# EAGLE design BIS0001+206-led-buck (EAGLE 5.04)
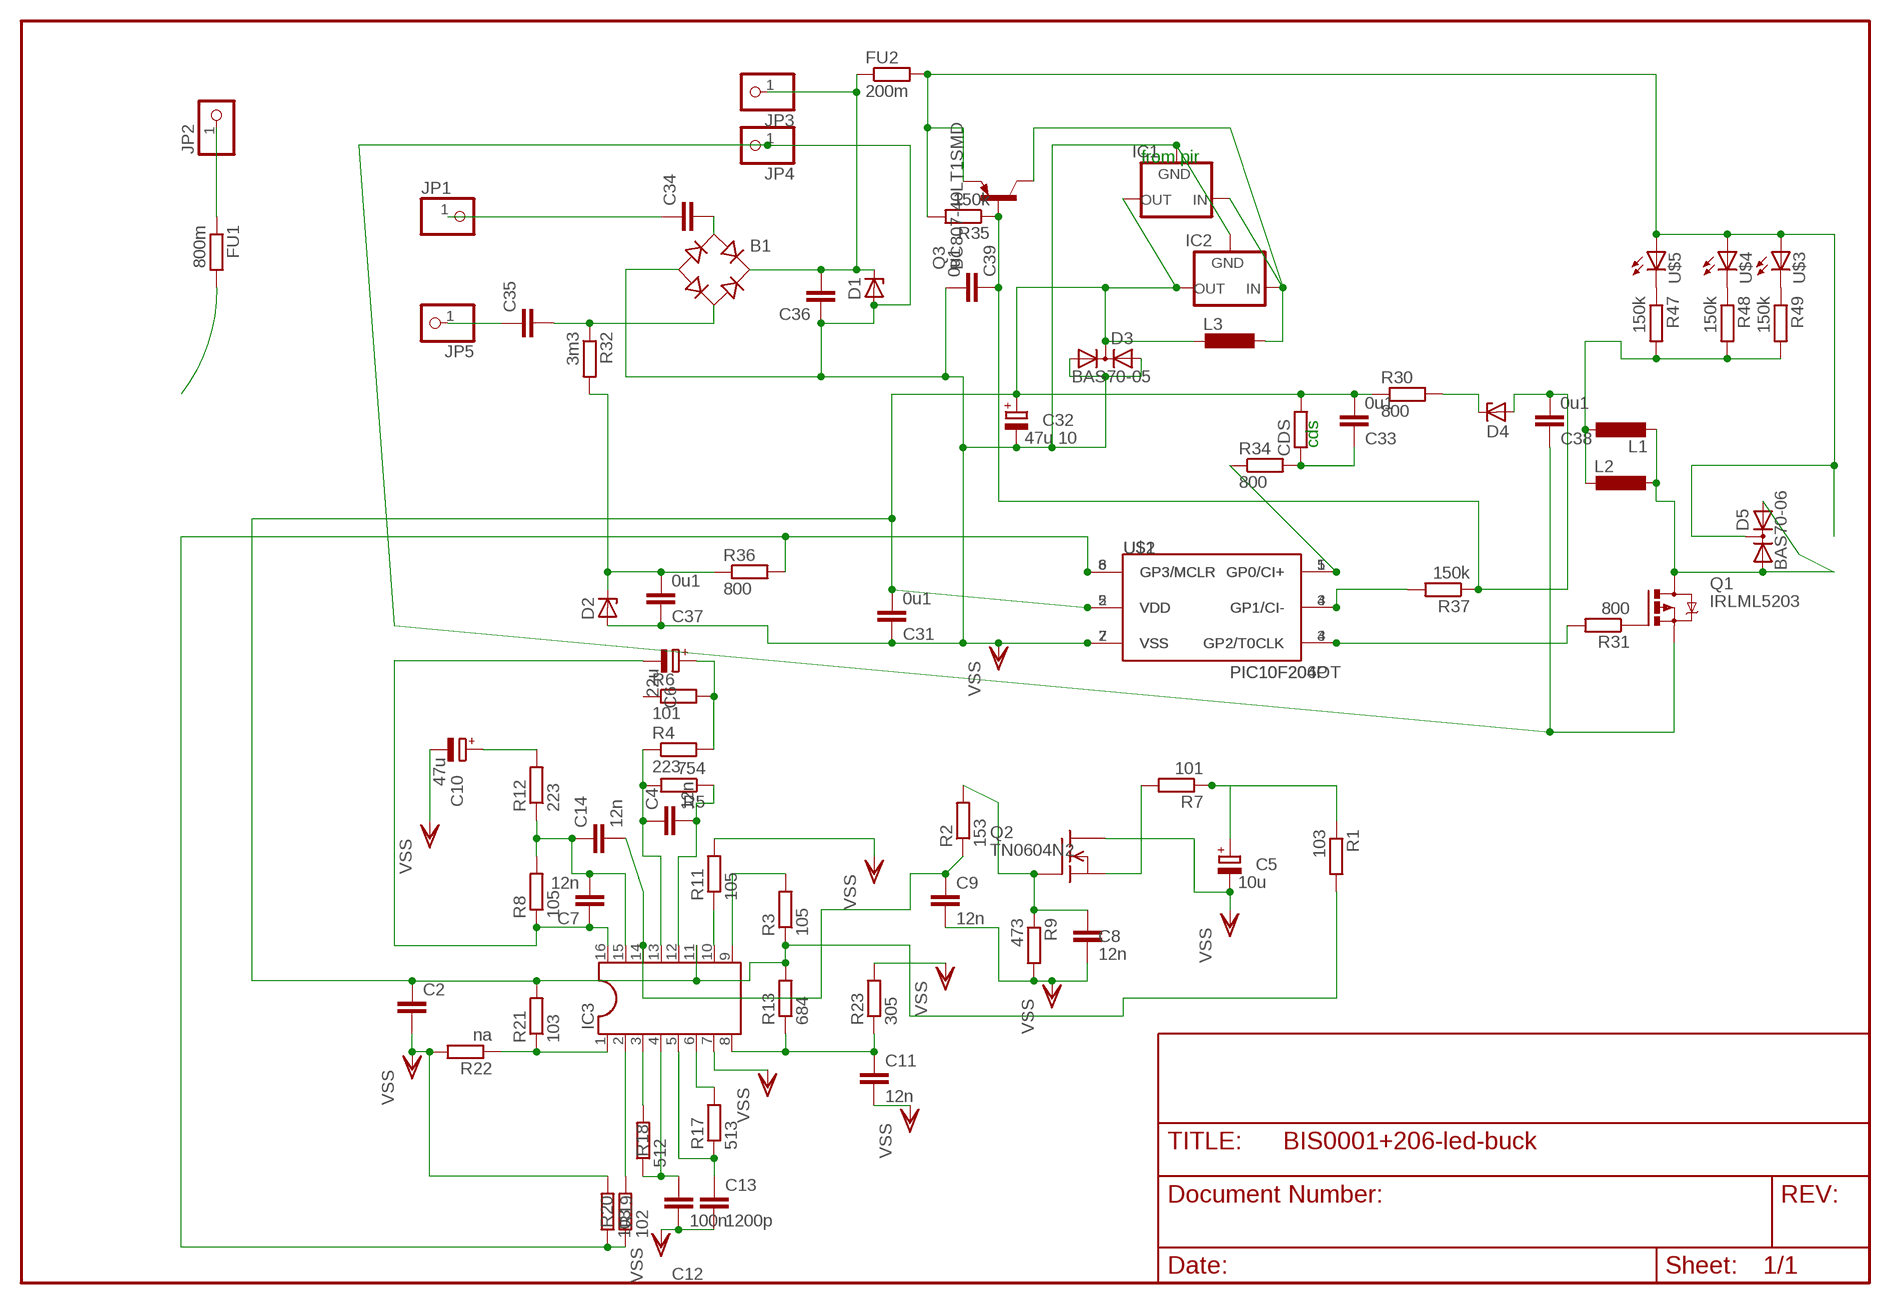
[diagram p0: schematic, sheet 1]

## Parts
B1  RB1A  [RB1A]
C2  C-EUC0805  [C0805]
C4  12n  C-EUC0805  [C0805]
C5  10u  CPOL-EUE2.5-5  [E2,5-5]
C6  22u  CPOL-EUE2.5-5  [E2,5-5]
C7  12n  C-EUC0805  [C0805]
C8  12n  C-EUC0805  [C0805]
C9  12n  C-EUC0805  [C0805]
C10  47u  CPOL-EUE2.5-5  [E2,5-5]
C11  12n  C-EUC0805  [C0805]
C12  100n  C-EUC0805  [C0805]
C13  1200p  C-EUC0805  [C0805]
C14  12n  C-EUC0805  [C0805]
C31  0u1  C-EUC1206  [C1206]
C32  47u 10  CPOL-EUE2.5-5  [E2,5-5]
C33  0u1  C-EUC1206  [C1206]
C34  C-EU050-025X075  [C050-025X075]
C35  C-EU050-025X075  [C050-025X075]
C36  C-EU050-025X075  [C050-025X075]
C37  0u1  C-EUC1206  [C1206]
C38  0u1  C-EUC1206  [C1206]
C39  0u1  C-EUC1206  [C1206]
CDS  R-EU_0207/5V  [0207/5V]
D1  ZENER-DIODEZD-7.5  [ZDIO-7.5]
D2  ZENER-DIODESOT23  [SOT23]
D3  BAS70-05  [SOT23]
D4  ZENER-DIODESOT23  [SOT23]
D5  BAS70-06  [SOT23]
FU1  800m  R-EU_0204/5  [0204/5]
FU2  200m  R-EU_0204/5  [0204/5]
IC1  XC63FPT  [TO92]
IC2  XC63FPP  [SOT89R]
IC3  DIL16SO16  [SO16]
JP1  PINHD-1X1  [1X01]
JP2  PINHD-1X1  [1X01]
JP3  PINHD-1X1  [1X01]
JP4  PINHD-1X1  [1X01]
JP5  PINHD-1X1  [1X01]
L1  L-EUL5650M  [L5650M]
L2  L-EU0207/7  [0207/7]
L3  L-EU0204V  [0204V]
Q1  IRLML5203  [MICRO3]
Q2  TN0604N2  [TO-39]
Q3  BC807-40LT1SMD  [SOT23-BEC]
R1  103  R-EU_R0805  [R0805]
R2  153  R-EU_R0805  [R0805]
R3  105  R-EU_R0805  [R0805]
R4  223  R-EU_R0805  [R0805]
R5  754  R-EU_R0805  [R0805]
R6  101  R-EU_R0805  [R0805]
R7  101  R-EU_R0805  [R0805]
R8  105  R-EU_R0805  [R0805]
R9  473  R-EU_R0805  [R0805]
R11  105  R-EU_R0805  [R0805]
R12  223  R-EU_R0805  [R0805]
R13  684  R-EU_R0805  [R0805]
R17  513  R-EU_R0805  [R0805]
R18  512  R-EU_R0805  [R0805]
R19  102  R-EU_R0805  [R0805]
R20  103  R-EU_R0805  [R0805]
R21  103  R-EU_R0805  [R0805]
R22  na  R-EU_R0805  [R0805]
R23  305  R-EU_R0805  [R0805]
R30  800  R-EU_R1206  [R1206]
R31  800  R-EU_R1206  [R1206]
R32  3m3  R-EU_R1206  [R1206]
R34  800  R-EU_R1206  [R1206]
R35  150k  R-EU_R0805  [R0805]
R36  800  R-EU_R1206  [R1206]
R37  150k  R-EU_R1206  [R1206]
R47  150k  R-EU_R1206  [R1206]
R48  150k  R-EU_R1206  [R1206]
R49  150k  R-EU_R1206  [R1206]
U$1  PIC10F206P  [DIL8]
U$2  PIC10F204OT  [SOT23-6]
U$3  LED5MM  [LED5MM]
U$4  LED5MM  [LED5MM]
U$5  LED5MM  [LED5MM]

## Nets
N$1: B1.+ C36.2 D1.C FU2.1 JP3.1
N$4: FU1.1 JP2.1
N$6: D4.3(C) R30.2
N$7: D5.3(C) FU2.2 Q3.E R35.2 U$3.A U$4.A U$5.A
N$8: C38.2 C39.1 D4.1(A) Q3.B R35.1 R37.1
N$9: FU1.2
N$10: Q1.1(G) R31.1
N$11: IC3.1 R21.1 R22.1
N$12: R19.1 R20.1 R36.2 U$1.8(GP3/MCLR) U$2.6(GP3/MCLR)
N$13: R37.2 U$1.4(GP1/CI-) U$2.3(GP1/CI-)
N$14: R31.2 U$1.3(GP2/T0CLK) U$2.4(GP2/T0CLK)
N$15: IC1.2(IN) IC2.2(IN) L3.1 Q3.C
N$16: C37.2 D2.3(C) R32.2 R36.1
N$17: C35.1 JP5.1
N$18: B1.AC2 C35.2 R32.1
N$20: C34.1 JP1.1
N$22: L1.1 L2.2 R47.2 R48.2 R49.2
N$23: C33.1 CDS.1 R34.2
N$24: IC3.2 R19.2
N$25: C12.1 IC3.4 R18.1
N$26: D5.1(A1) D5.2(A2) L1.2 L2.1 Q1.3(D)
N$27: IC3.3 R18.2
N$28: C11.1 IC3.8 R13.1 R23.1
N$29: R34.1 U$1.5(GP0/CI+) U$2.1(GP0/CI+)
N$30: C13.1 IC3.5 R17.1
N$31: IC3.6 R17.2
N$32: IC3.10 R11.1
N$33: B1.AC1 C34.2
N$34: C4.2 IC3.12 R5.1
N$35: C4.1 IC3.13 R4.1 R5.2
N$36: IC3.9 R3.2
N$37: C6.+ R4.2 R6.2
N$38: R47.1 U$5.K(C)
N$39: C9.1 C14.2 IC3.14 R2.1
N$40: C7.2 C14.1 IC3.15 R8.2 R12.1
N$41: C6.- C7.1 IC3.16 R8.1
N$42: Q2.1(S) R7.2
N$43: C5.+ R1.1 R7.1
N$44: C10.+ R12.2
N$46: C8.1 Q2.2(G) R2.2 R9.1
N$54: R48.1 U$4.K(C)
N$55: R49.1 U$3.K(C)
V2CC: C2.1 C31.2 C32.+ C33.2 CDS.2 D3.3(C) IC1.3(OUT) IC2.3(OUT) IC3.11 L3.2 R1.2 R3.1 R13.2 R21.2 R30.1 U$1.2(VDD) U$2.5(VDD)
VSS: B1.- C2.2 C5.- C8.2 C9.2 C10.- C11.2 C12.2 C13.2 C31.1 C32.- C36.1 C37.1 C38.1 C39.2 D1.A D2.1(A) D3.1(A1) D3.2(A2) IC1.1(GND) IC2.1(GND) IC3.7 JP4.1 Q1.2(S) Q2.3(D) R9.2 R11.2 R20.2 R22.2 R23.2 U$1.7(VSS) U$2.2(VSS)
Unconnected: R6.1

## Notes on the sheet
- from pir
- cds

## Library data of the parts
B1 = rectifier:RB1A: RECTIFIER 1 A
C2 C4 C7-C9 C11-C14 = rcl-2:C-EU: CAPACITOR, European symbol
C5 C6 C10 C32 = rcl:CPOL-EU: POLARIZED CAPACITOR, European symbol
C31 C33-C39 = rcl:C-EU: CAPACITOR, European symbol
CDS = rcl(2):R-EU_: RESISTOR, European symbol
D1 D2 D4 = diode-1:ZENER-DIODE: Z-Diode
D3 = diode-1:BAS70-05: Silicon Schottky Diodes General-purpose diode for high-speed switching
D5 = diode-1:BAS70-06: Silicon Schottky Diodes General-purpose diode for high-speed switching
FU1 FU2 R30-R32 R34-R37 R47-R49 = rcl:R-EU_: RESISTOR, European symbol
IC1 IC2 = v-reg:XC63FP: Positiv Voltage Regulators www.torex.co.jp/english/product/pro02/pdf/0201_xc62fp.pdf
IC3 = ic-package:DIL16: Dual In Line / Socket
JP1-JP5 = pinhead:PINHD-1X1: PIN HEADER
L1 = rcl-2:L-EU: INDUCTOR, European symbol
L2 L3 = rcl:L-EU: INDUCTOR, European symbol
Q1 = transistor-power:IRLML5203: HEXFET P-Channel Power MOSFET
Q2 = transistor-fet:TN0604N2: N-Channel Enhancement MOSFET 40V; 4A; 0,85Ohm
Q3 = transistor-pnp:BC807*: PNP Transistror
R1-R9 R11-R13 R17-R23 = rcl-2:R-EU_: RESISTOR, European symbol
U$1 U$2 = microchip-3:PIC10F2*: uPC nW 0,25/0,5k Program Flash memory Comparator
U$3-U$5 = led(3):LED: LED

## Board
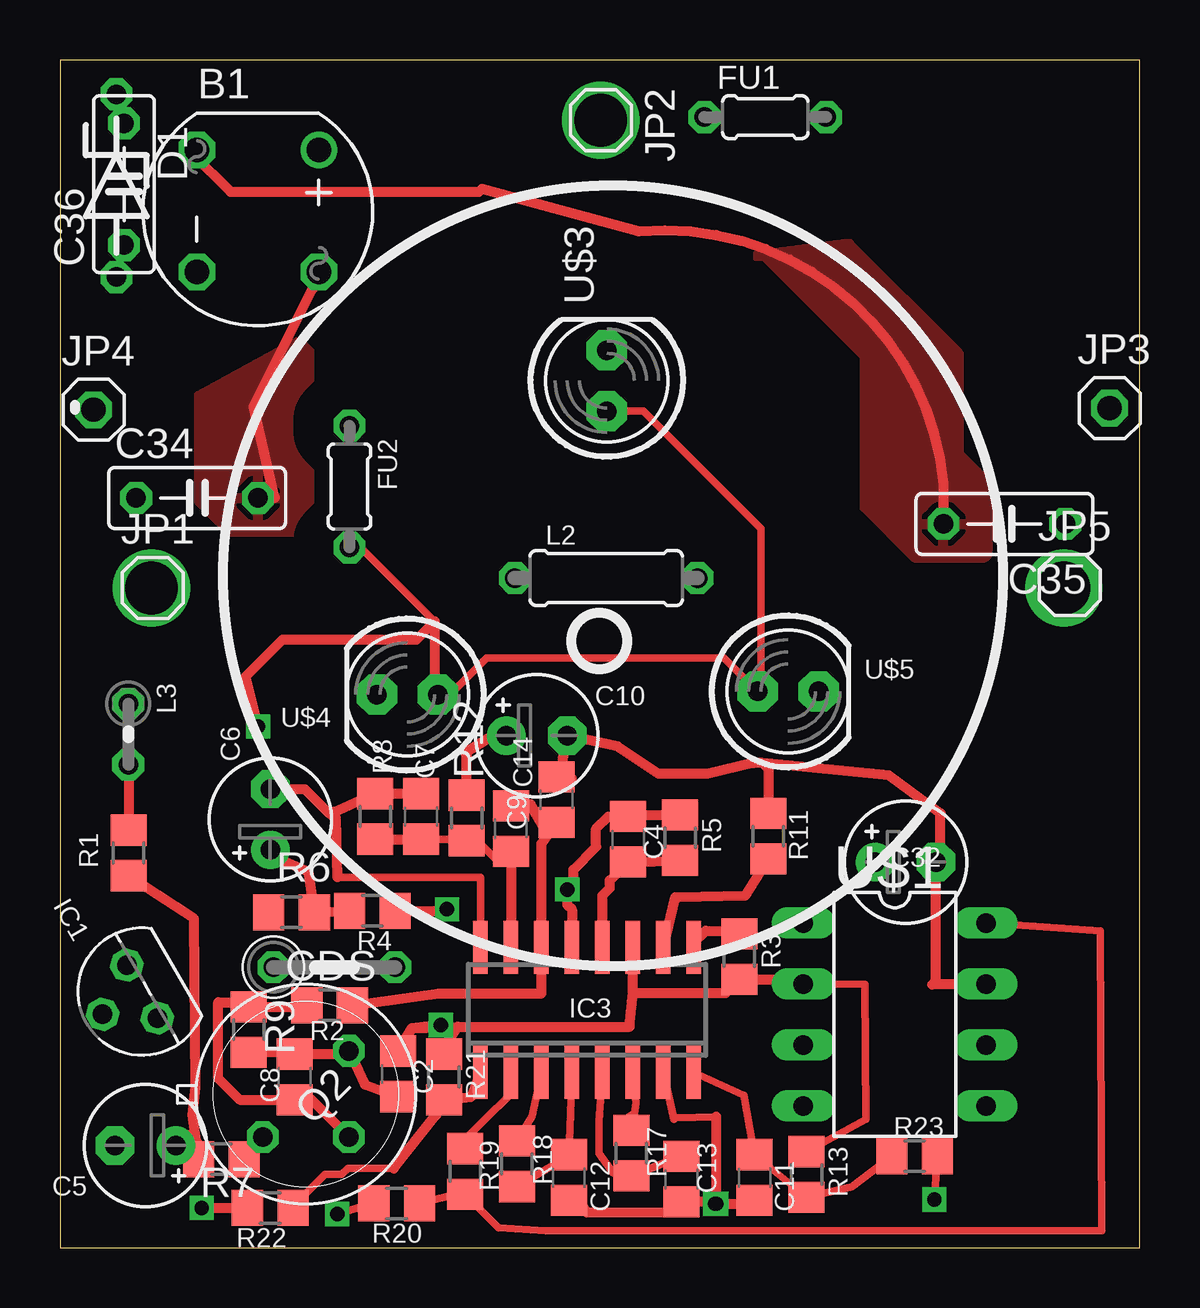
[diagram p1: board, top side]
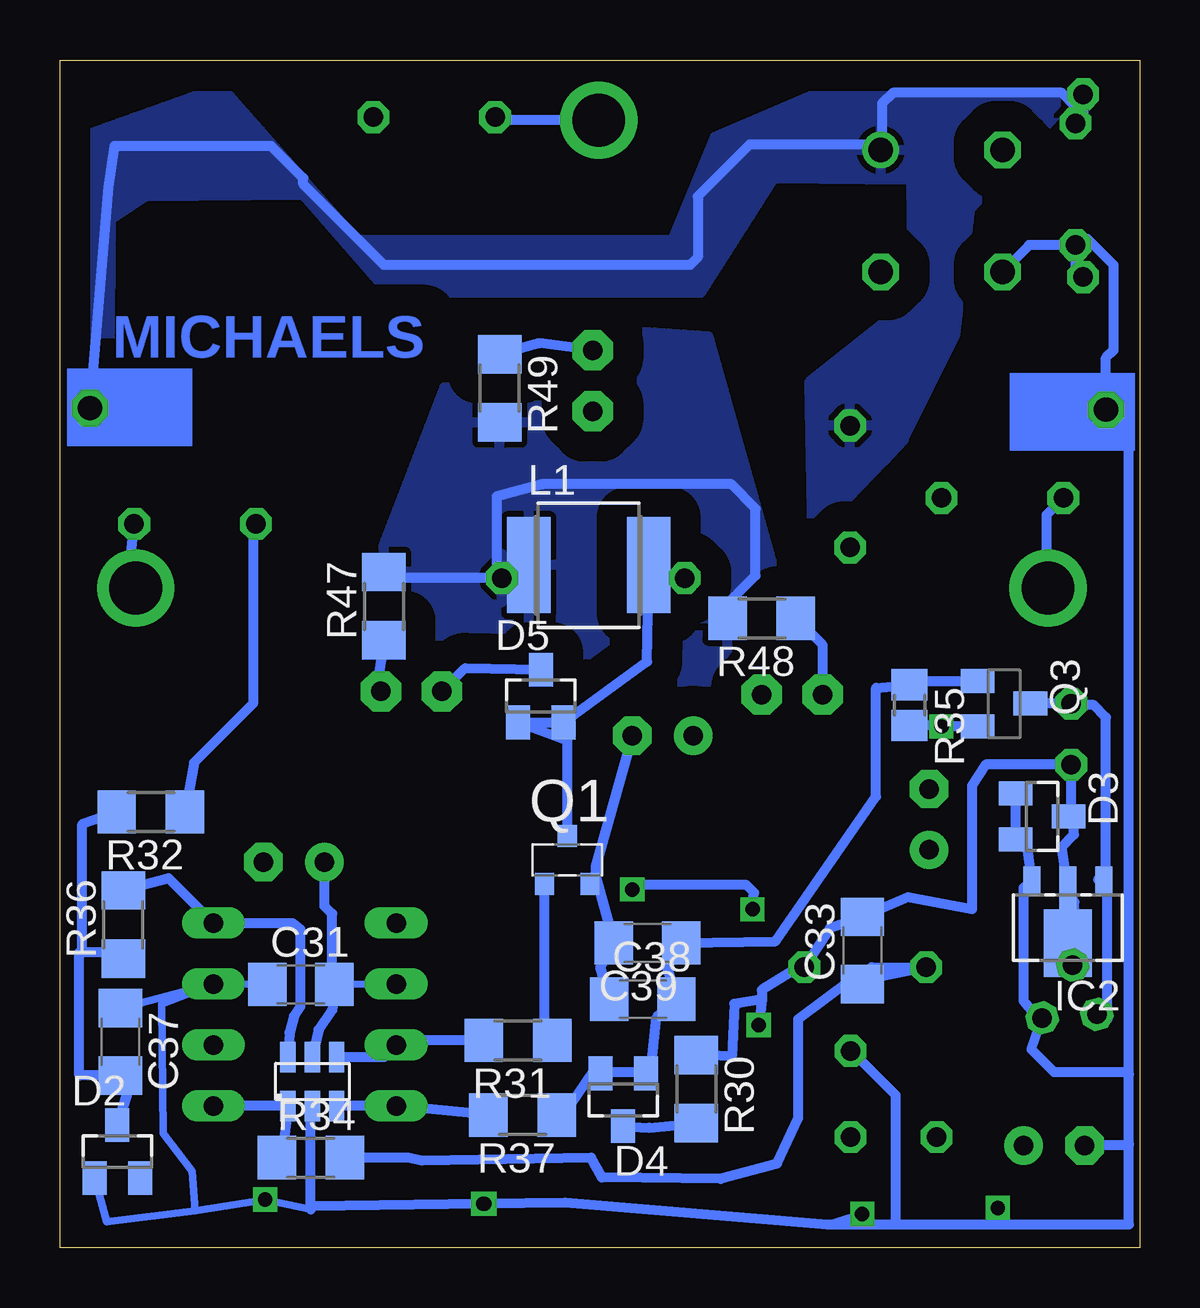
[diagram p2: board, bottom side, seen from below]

Size 45 x 49.5 mm. Coordinates in mm from the lower left corner, seen from the top.
Outline: 0,0 45,0 45,49.5 0,49.5 0,0
Copper layers (1*16): Top 0.035mm / dielectric 1.5mm / Bottom 0.035mm
Design rules "default": minimum track width 10mil, minimum drill 24mil, track to track 8mil, track to pad 8mil, pad to pad 8mil, via to via 8mil, smd to smd 8mil, copper to edge 40mil, drill to drill 8mil, minimum pad ring 10mil, minimum via ring 8mil, stop-mask expansion 4mil, vias tented up to drill 0mil, thermal gap 10mil

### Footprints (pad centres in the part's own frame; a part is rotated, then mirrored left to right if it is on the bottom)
RB1A = drill 1.016 round: + -2.54,2.54 | drill 1.016 octagon: - 2.54,-2.54; AC1 2.54,2.54; AC2 -2.54,-2.54
C0805 = smd 1.3 x 1.5: 1 -0.95,0; 2 0.95,0
E2,5-5 = drill 0.813 pad 1.6 round: + -1.27,0 | drill 0.813 pad 1.6 octagon: - 1.27,0
C1206 = smd 1.6 x 1.8: 1 -1.4,0; 2 1.4,0
C050-025X075 = drill 0.813 octagon: 1 -2.54,0; 2 2.54,0
0207/5V = drill 0.813 octagon: 1 -2.54,0; 2 2.54,0
ZDIO-7.5 = drill 0.813 octagon: A 3.81,0; C -3.81,0
SOT23 = smd 1 x 1.4: 1 -0.95,-1.1; 2 0.95,-1.1; 3 0,1.1
0204/5 = drill 0.813 octagon: 1 -2.54,0; 2 2.54,0
TO92 = drill 0.813 octagon: 1 -1.27,0; 2 0,1.905; 3 1.27,0
SOT89R = smd 0.7 x 1.1: 1 1.5,-1.75; 2 -1.5,-1.75 | smd 0.7 x 1.8: 3 0,-1.4 | smd 2 x 2.8: 4 0,0.9
SO16 = smd 0.6 x 2.2: 1 -4.445,-2.6; 2 -3.175,-2.6; 3 -1.905,-2.6; 4 -0.635,-2.6; 5 0.635,-2.6; 6 1.905,-2.6; 7 3.175,-2.6; 8 4.445,-2.6; 9 4.445,2.6; 10 3.175,2.6; 11 1.905,2.6; 12 0.635,2.6; 13 -0.635,2.6; 14 -1.905,2.6; 15 -3.175,2.6; 16 -4.445,2.6
1X01 = drill 1.016 octagon: 1 0,0
L5650M = smd 1.8 x 4: 1 -2.5,0; 2 2.5,0
0207/7 = drill 0.813 octagon: 1 -3.81,0; 2 3.81,0
0204V = drill 0.813 octagon: 1 -1.27,0; 2 1.27,0
MICRO3 = smd 0.8 x 0.9: 1 -0.95,-1; 2 0.95,-1; 3 0,1
TO-39 = drill 0.813 octagon: 1 0,-2.54; 2 2.54,0; 3 0,2.54
SOT23-BEC = smd 1 x 1.4: B -0.95,-1.1; C 0,1.1; E 0.95,-1.1
R0805 = smd 1.3 x 1.5: 1 -0.95,0; 2 0.95,0
R1206 = smd 1.6 x 1.803: 1 -1.422,0; 2 1.422,0
R0805' = smd 1.3 x 1.5: 1 -0.85,0; 2 0.85,0
DIL8 = drill 0.813 long: 1 -3.81,-3.81; 2 -1.27,-3.81; 3 1.27,-3.81; 4 3.81,-3.81; 5 3.81,3.81; 6 1.27,3.81; 7 -1.27,3.81; 8 -3.81,3.81
SOT23-6 = smd 0.635 x 1.27: 1 -1.016,-1.016; 2 0,-1.016; 3 1.016,-1.016; 4 1.016,1.016; 5 0,1.016; 6 -1.016,1.016
LED5MM = drill 0.813 pad 1.676 octagon: A -1.27,0; K 1.27,0

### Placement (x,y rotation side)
B1  8.25,43.21 270 top
C2  14.1,7.24 270 top
C4  23.69,17.02 270 top
C5  3.56,4.25 180 top
C6  8.76,17.84 90 top
C7  15.05,17.97 270 top
C8  9.78,7.11 90 top
C9  20.7,18.67 90 top
C10  19.88,21.34 0 top
C11  28.96,2.92 270 top
C12  21.21,2.92 270 top
C13  25.91,2.86 270 top
C14  18.8,17.46 90 top
C31  34.96,10.96 0 bottom
C32  35.24,16.07 0 top
C33  11.56,12.38 90 bottom
C34  5.71,31.24 0 top
C35  39.37,30.16 180 top
C36  2.67,44.32 90 top
C37  42.48,8.57 270 bottom
C38  20.7,10.35 0 bottom
C39  20.51,12.7 180 bottom
CDS  11.43,11.68 0 top
D1  2.35,44.26 270 top
D2  42.61,4 0 bottom
D3  4.06,17.97 270 bottom
D4  21.53,6.16 180 bottom
D5  24.96,22.99 0 bottom
FU1  29.4,47.12 0 top
FU2  12.07,31.72 270 top
IC1  3.42,10.67 120 top
IC2  2.98,13.59 180 bottom
IC3  21.97,9.91 0 top
JP1  3.87,27.5 0 top
JP2  22.54,46.99 270 top
JP3  43.75,34.99 0 top
JP4  1.4,34.92 0 top
JP5  42.1,27.62 0 top
L1  22.96,28.44 0 bottom
L2  22.77,27.91 0 top
L3  2.85,21.4 270 top
Q1  23.85,16.16 0 bottom
Q2  10.25,6.4 315 top
Q3  5.65,22.67 270 bottom
R1  2.86,16.45 90 top
R2  11.24,10.1 180 top
R3  28.32,12.13 90 top
R4  13.02,14.03 180 top
R5  25.84,17.08 90 top
R6  9.65,13.97 0 top
R7  6.73,3.68 0 top
R8  13.14,17.97 270 top
R9  7.87,9.08 270 top
R11  29.53,17.14 90 top
R12  16.95,17.91 90 top
R13  31.11,3.05 90 top
R17  23.81,3.94 90 top
R18  19.05,3.49 90 top
R19  16.89,3.17 90 top
R20  14.03,1.84 180 top
R21  16,7.11 90 top
R22  8.76,1.65 180 top
R23  35.62,3.81 0 top
R30  18.48,6.6 270 bottom
R31  25.91,8.64 180 bottom
R32  41.21,18.16 180 bottom
R34  34.54,3.75 0 bottom
R35  150k  [R0805']  9.59,22.61 270 bottom
R36  42.35,13.46 90 bottom
R37  25.72,5.52 180 bottom
R47  31.5,26.73 90 bottom
R48  15.75,26.23 180 bottom
R49  26.67,35.81 270 bottom
U$1  34.8,9.72 270 top
U$2  34.48,6.92 0 bottom
U$3  22.8,36.13 90 top
U$4  14.48,23.05 180 top
U$5  30.35,23.18 0 top

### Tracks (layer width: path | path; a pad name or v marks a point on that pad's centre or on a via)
N$1
  Bottom 0.406: JP3.1 42.99,44.2 42.74,45.91 36.2,45.91 34.86,44.58 34.86,44.32 31.5,40.96 18.73,40.96 18.41,41.27 18.41,43.81 16.26,45.97 11.2,45.97 B1.+ 10.73,45.8 10.73,47.69 10.29,48.13 3.24,48.13 2.67,47.56 C36.2 2.35,47.18 D1.C
  pour Bottom (isolate 1.27, rank 2): 1.52,49.34 9.97,49.59 17.72,46.29 19.49,42 32.64,42 38.29,48.39 44.89,46.04 44.7,36.96 42.93,37.08 42.86,42.86 41.4,43.81 34.86,43.88 31.31,39.8 18.29,39.8 15.24,44.58 9.53,44.51 9.46,39.5 13.78,36.07 13.65,29.65 10.67,32.77 9.84,33.66 7.68,38.04 7.05,43.31
N$2  (via drill 2.2)
  other vias: 3.81,27.5
N$3  (via drill 2.2)
  other vias: 41.85,27.5
N$4
  Bottom 0.406: JP2.1 26.73,46.99 FU1.1
N$5  (via drill 2.2)
  other vias: 22.54,46.99
N$6
  Bottom 0.406: R30.2 20.44,4.99 D4.3
N$7  (via drill 0.6)
  Top 0.305: FU2.2 12.54,29.18 15.62,26.1 | U$3.A 24.32,34.86 29.21,29.97 29.21,23.3 U$5.A 27.69,24.57 17.78,24.57 16.26,23.05 U$4.A
  Top 0.406: v8.26,21.72 7.75,23.81 9.27,25.34 14.86,25.34 15.62,26.1 15.62,23.18 U$4.A
  Bottom 0.406: D5.3 28.11,24.15 U$5.A | Q3.E 6.79,21.72 v8.26,21.72 8.29,21.76 R35.2
N$8
  Bottom 0.406: R37.1 24,5.52 22.8,7.3 20.6,7.3 D4.1 20.39,7.43 20.32,7.81 20.13,9.59 C38.2 19.68,11.68 C39.1 15.17,12.77 10.99,18.8 10.99,23.33 R35.1 9.43,23.62 Q3.B
N$10
  Bottom 0.406: R31.1 24.8,8.64 Q1.1
N$11
  Top 0.305: 9.71,1.71 11.05,3.05 11.75,3.05 12,3.3 13.91,3.3
  Top 0.406: IC3.1 17.15,6.29 R21.1 15.68,5.84 15.68,5.52 13.91,3.3 | R22.1 9.71,1.71
N$12
  Top 0.305: R20.1 16.76,2.29 R19.1 18.29,0.83 20.26,0.7 43.43,0.7 43.37,13.21 U$1.8
  Bottom 0.406: U$1.8 35.31,13.53 34.99,13.27 34.99,10.03 35.24,9.65 35.43,8.95 U$2.6 | U$1.8 39.47,13.14 | R36.2 40.47,15.39 U$1.8
N$13
  Bottom 0.406: R37.2 U$1.4 U$2.3
N$14
  Bottom 0.406: U$2.4 31.5,7.94 U$1.3 30.99,8.64 R31.2 27.27,8.06
N$15
  Bottom 0.406: IC1.2 1.58,9.34 1.33,9.53 1.33,14.93 IC2.2 1.74,15.34 1.4,15.68 1.4,22.1 1.91,22.61 2.78,22.61 L3.1 Q3.C
N$16
  Bottom 0.406: 44.07,12.32 44.2,12.32 44.2,7.17 C37.2 42.1,6.79 D2.3 | 44.07,12.32 42.35,12.32 R36.1 | R32.2 44.07,17.65 44.07,12.32
N$17
  Bottom 0.406: JP5.1 42.1,28.32 C35.1
N$18
  Top 0.406: B1.AC2 5.52,45.6 7.11,44.01 17.46,44.01 17.59,44.13 24.13,42.35 arc-90 36.83,31.81 C35.2
  Bottom 0.406: R32.1 39.41,20.22 36.96,22.67 36.96,30.04 C35.2
  pour Top (isolate 0.61): 29.02,41.34 29.34,41.34 33.53,37.15 33.53,30.86 35.62,28.77 38.54,28.77 38.67,28.89 38.67,31.88 37.47,33.08 37.47,37.27 32.89,41.85
N$20
  Bottom 0.406: JP1.1 3.87,30.54 C34.1
N$22
  Bottom 0.406: L2.2 31.25,27.91 R47.2 | R48.2 17.17,26.84 16,28 16,30.8 17.02,31.81 24.89,31.81 26.8,31.3 26.8,28.13 L2.2 | L1.1 26.23,28.25 L2.2
  pour Bottom (isolate 1.27, rank 2): 21.97,38.29 28.07,38.23 36.07,17.46 12.19,17.4 17.97,37.97 21.59,38.23
N$23
  Bottom 0.406: C33.1 11.05,11.24 CDS.1 11.18,11.68 11.68,11.18 12,11.18 14.22,9.53 14.22,5.4 15.11,3.49 17.46,2.86 22.42,2.92 22.86,3.75 29.91,3.62 30.48,3.75 R34.2
N$24
  Top 0.305: IC3.2 18.67,6.29 17.78,5.4 17.02,4.63 R19.2
N$25
  Top 0.305: IC3.4 C12.1 20.45,3.37 R18.1
N$26
  Bottom 0.406: Q1.3 23.85,21.1 D5.1 D5.2 20.52,24.42 L1.2 20.18,27.91 L2.1
N$27
  Top 0.305: IC3.3 19.68,5.46 R18.2
N$28
  Top 0.305: IC3.8 28.51,6.35 C11.1 R13.1 33.02,2.54 R23.1
N$29
  Bottom 0.406: U$1.5 U$2.1 35.75,3.71 R34.1
N$30
  Top 0.305: IC3.5 22.48,5.27 22.48,3.94 23.05,3.11 R17.1 C13.1
N$31
  Top 0.305: IC3.6 24,6.03 23.94,5.59 23.43,5.27 R17.2
N$32
  Top 0.406: IC3.10 25.65,14.61 25.78,14.61 28.57,14.67 R11.1
N$33
  Top 0.406: C34.2 8.95,31.24 8.06,35.05 10.54,39.96 B1.AC1
  pour Top (isolate 1.676): 5.78,35.5 5.78,31.11 7.05,29.84 9.84,29.84 10.41,30.42 10.41,37.34 9.97,37.78
N$34
  Top 0.406: IC3.12 22.61,14.67 22.92,14.99 22.92,15.31 C4.2 24.32,16.07 R5.1
N$35  (via drill 0.6)
  Top 0.406: R4.1 15.88,14.03 v16.13,14.1 | IC3.13 21.34,14.1 21.14,14.29 v21.14,14.92 21.4,15.18 21.4,15.75 22.35,16.7 22.35,17.46 22.86,17.97 23.18,17.97 | 23.18,17.97 C4.1 | R5.2 23.24,18.03 23.18,17.97
  Bottom 0.406: v16.13,14.1 16.07,14.8 16.38,15.11 20.95,15.11 v21.14,14.92
N$36
  Top 0.406: IC3.9 26.42,12.7 26.92,13.21 28.19,13.21 R3.2
N$37
  Top 0.406: R4.2 R6.2 10.35,15.68 9.02,16.26 9.21,16.45 C6.+
N$38
  Bottom 0.406: U$5.K 31.81,23.18 R47.1
N$39
  Top 0.406: R2.1 15.78,10.59 20.07,10.59 IC3.14 20.07,16.83 C9.1 20.13,17.59 19.62,18.48 19.12,18.16 C14.2
N$40
  Top 0.305: C7.2 16.89,17.02 R12.1 17.4,16.96 18.16,16.19 18.48,16.19 C14.1
  Top 0.406: R8.2 C7.2 | C14.1 IC3.15
N$41
  Top 0.305: IC3.16 17.53,15.43 11.56,15.43
  Top 0.406: 11.56,15.43 11.49,17.91 11.21,18.11 | 11.21,18.11 11.43,18.16 R8.1 C7.1 | C6.- 10.21,19.11 11.21,18.11
N$42
  Top 0.305: Q2.1 R7.2
N$43
  Top 0.406: R1.1 5.59,13.72 5.65,6.67 5.53,5.53 R7.1 5.78,4.25 5.52,4.7 4.83,4.7 C5.+
N$44
  Top 0.406: C10.+ 18.03,21.34 16.89,20.64 16.95,20.51 R12.2
N$46
  Top 0.406: R2.2 10.22,10.03 R9.1 7.68,10.22 6.6,10.22 6.6,7.05 7.49,6.16 C8.1 10.49,6.16 Q2.2
N$54
  Bottom 0.406: 13.27,22.99 U$4.K 13.21,25.11 R48.1
N$55
  Bottom 0.406: U$3.K 25.02,37.69 R49.1
V2CC  (via drill 0.6)
  Top 0.305: R13.2 33.59,5.33 C31.2 U$1.2
  Top 0.406: 23.88,10.6 IC3.11 | 23.88,10.6 23.75,9.21 16.57,9.21 | 14.67,9.14 16.57,9.21 | 14.67,9.14 C2.1 | R21.2 16.19,8.64 16.57,9.21 | 23.88,10.6 27.75,10.6 R3.1 30.8,11.18 U$1.2 | R1.2 2.86,20.12 L3.2 | v15.88,9.27 14.67,9.14
  Bottom 0.305: U$1.2 C31.2
  Bottom 0.406: U$2.5 34.23,9.08 33.66,9.91 33.59,10.36 C31.2 33.66,11.06 33.66,13.91 33.97,14.22 C32.+ | IC1.3 2.71,14.4 IC2.3 3.24,16.7 2.73,17.21 2.73,17.74 D3.3 2.85,18.09 L3.2 6.41,20.13 6.99,19.24 6.99,14.1 9.65,14.6 C33.2 12.89,13.33 CDS.2 14.22,11.68 15.75,10.73 15.75,10.35 | R30.1 16.99,7.96 16.89,10.16 15.75,10.35 | 15.75,10.35 v15.88,9.27
VSS  (via drill 0.6)
  Top 0.305: v11.56,1.4 R20.2 | C13.2 26.01,1.9 | IC3.7 25.59,5.33 25.65,5.4 27.36,5.45 | v36.45,2 R23.2
  Top 0.406: C2.2 12.7,6.8 Q2.3 11.91,8.06 C8.2 9.71,8.13 R9.2 | v5.91,1.65 R22.2 | C10.- 23.24,20.89 24.96,19.75 26.99,19.75 28.89,20.19 29.27,20.19 | C9.2 21.34,19.56 20.95,19.94 20.95,20.38 C10.- | U$1.7 38.59,10.96 C31.1 36.51,11.12 C32.- 36.7,16.26 36.7,18.1 34.54,19.68 29.27,20.19 | R11.2 29.53,19.94 29.27,20.19 | C10.- 21.21,21.27 | v27.3,1.82 27.22,1.91 C13.2 25.71,1.45 21.96,1.45 21.69,1.97 C12.2 | 27.36,5.45 v27.36,1.82 28.81,1.82 C11.2
  Bottom 0.305: 13.02,0.95 v11.56,1.4 | 34.54,1.59 v36.45,2 39.37,1.52 | U$1.7 C31.1 | U$1.7 C37.1 | U$1.7 40.77,10.16 40.7,4.76 39.5,3.17 39.37,1.52 | D2.1 43.05,1.08 39.37,1.52
  Bottom 0.406: U$2.2 34.54,5.91 34.54,1.71 | 34.54,1.71 34.54,1.59 | 5.91,0.95 0.45,0.95 0.45,4.32 | 5.91,0.95 10.16,0.95 | 10.16,0.95 13.02,0.95 23.94,1.87 v27.3,1.82 | v27.3,1.82 v27.36,1.82 | v27.36,1.82 34.54,1.71 | 0.45,4.32 0.45,7.24 | 0.45,7.24 0.45,34.04 1.4,34.04 JP4.1 1.4,37.08 1.08,37.4 1.08,40.96 2.16,42.04 2.41,42.04 C36.1 | D3.1 D3.2 4.74,17.15 IC2.1 4.83,15 4.83,10.29 4.51,9.91 IC1.1 4.51,8.26 3.56,7.3 0.51,7.3 0.45,7.24 | C5.- 0.51,4.25 0.45,4.32 | Q2.3 12.01,8.2 10.16,6.35 10.16,0.95 | 5.91,0.95 v5.91,1.65 | C38.1 22.48,11.68 C39.2 22.67,15.5 | 22.67,15.5 Q1.2 | 22.67,15.5 22.67,15.87 C10.- | C36.1 4.59,41.78 B1.- | C36.1 2.67,41.91 | C36.1 2.67,40.77 D1.A | v27.3,1.82 v27.36,1.82
(copper drawn outside any net)
  shapes: Bottom area x2

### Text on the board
Bottom: MICHAELS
